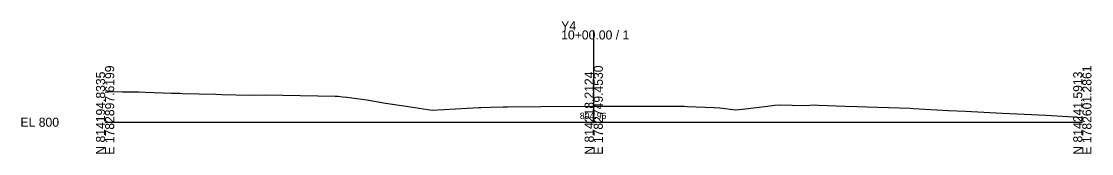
# Model space of a CAD drawing. Extents: x -26 to 3903, y -10 to 9562.
# Drawn here: x -25.7 to 302.8, y -9.7 to 31.1 of the extents above; entities that cross this region are included whole.
import ezdxf

# ---------------------------------------------------------------- set-up
doc = ezdxf.new("R2010")
doc.units = 0
for name, color, linetype in [('Exist Cross Section Cell', 7, 'Continuous'), ('Exist XS Center Line Elevation Label', 7, 'Continuous'), ('Exist XS Ground Line', 7, 'Continuous')]:
    doc.layers.add(name, color=color, linetype=linetype)

msp = doc.modelspace()

# ---------------------------------------------------------------- linework, layer by layer
at = {"layer": 'Exist Cross Section Cell'}
for p, q in [((150, 0), (150, 28.3)), ((0, 0), (150, 0)), ((150, 0), (300, 0))]:
    msp.add_line(p, q, dxfattribs=at)
at = {"layer": 'Exist XS Ground Line'}
for p, q in [((0, 9.28), (2.09, 9.43)), ((2.09, 9.43), (5.35, 9.39)), ((5.35, 9.39), (10.29, 9.35)), ((10.29, 9.35), (12.25, 9.3)), ((12.25, 9.3), (20.39, 8.99)), ((20.39, 8.99), (22.95, 8.91)), ((22.95, 8.91), (23.76, 8.89)), ((23.76, 8.89), (33.96, 8.68)), ((33.96, 8.68), (35.82, 8.59)), ((35.82, 8.59), (44.52, 8.38)), ((44.52, 8.38), (49.2, 8.4)), ((49.2, 8.4), (70.59, 8.04)), ((70.59, 8.04), (71.5, 8.01)), ((71.5, 8.01), (72.89, 7.8)), ((72.89, 7.8), (74.17, 7.69)), ((74.17, 7.69), (80.33, 6.85)), ((80.33, 6.85), (86.11, 5.88)), ((86.11, 5.88), (92.44, 4.97)), ((92.44, 4.97), (100.37, 3.72)), ((100.37, 3.72), (107.56, 4.1)), ((107.56, 4.1), (114.78, 4.54)), ((114.78, 4.54), (115.34, 4.56)), ((115.34, 4.56), (118.36, 4.65)), ((118.36, 4.65), (122.17, 4.75)), ((122.17, 4.75), (123.23, 4.78)), ((123.23, 4.78), (123.54, 4.79)), ((123.54, 4.79), (133.79, 4.83)), ((133.79, 4.83), (149.32, 4.96)), ((149.32, 4.96), (150, 4.96)), ((150, 4.96), (151.29, 4.96)), ((151.29, 4.96), (153.18, 4.96)), ((153.18, 4.96), (168.31, 4.93)), ((168.31, 4.93), (177.34, 4.92)), ((177.34, 4.92), (177.8, 4.9)), ((177.8, 4.9), (178.67, 4.86)), ((178.67, 4.86), (186.94, 4.52)), ((186.94, 4.52), (188.68, 4.39)), ((188.68, 4.39), (193.5, 3.8)), ((193.5, 3.8), (195.66, 4.03)), ((195.66, 4.03), (203.3, 4.96)), ((203.3, 4.96), (205.47, 5.21)), ((205.47, 5.21), (206.9, 5.32)), ((206.9, 5.32), (214.94, 5.17)), ((214.94, 5.17), (217.87, 5.31)), ((217.87, 5.31), (219.05, 5.29)), ((219.05, 5.29), (227.24, 4.99)), ((227.24, 4.99), (230.85, 4.85)), ((230.85, 4.85), (233.89, 4.71)), ((233.89, 4.71), (247.17, 4.33)), ((247.17, 4.33), (248.2, 4.28)), ((248.2, 4.28), (258.94, 3.63)), ((258.94, 3.63), (264.08, 3.36)), ((264.08, 3.36), (275.34, 2.81)), ((275.34, 2.81), (277.73, 2.66)), ((277.73, 2.66), (288.75, 2.17)), ((288.75, 2.17), (295.68, 1.73)), ((295.68, 1.73), (300, 1.48))]:
    msp.add_line(p, q, dxfattribs=at)

# ---------------------------------------------------------------- texts
at = {"layer": 'Exist Cross Section Cell'}
for s, p in [('Y4', (140, 28.3)), ('10+00.00 / 1', (140, 25.5)), ('EL 800', (-26, -1.4))]:
    msp.add_text(s, height=2.8, dxfattribs=at).set_placement(p)
for s, p in [('E 1782897.6199', (2.8, -10)), ('E 1782749.4530', (152.8, -10)), ('E 1782601.2861', (302.8, -10)), ('N 814194.8335', (0, -10)), ('N 814218.2124', (150, -10)), ('N 814241.5913', (300, -10))]:
    msp.add_text(s, height=2.8, rotation=90, dxfattribs=at).set_placement(p)
at = {"layer": 'Exist XS Center Line Elevation Label'}
msp.add_text('804.96', height=2, dxfattribs=at).set_placement((145.73, 0.96))

doc.saveas('drawing.dxf')
